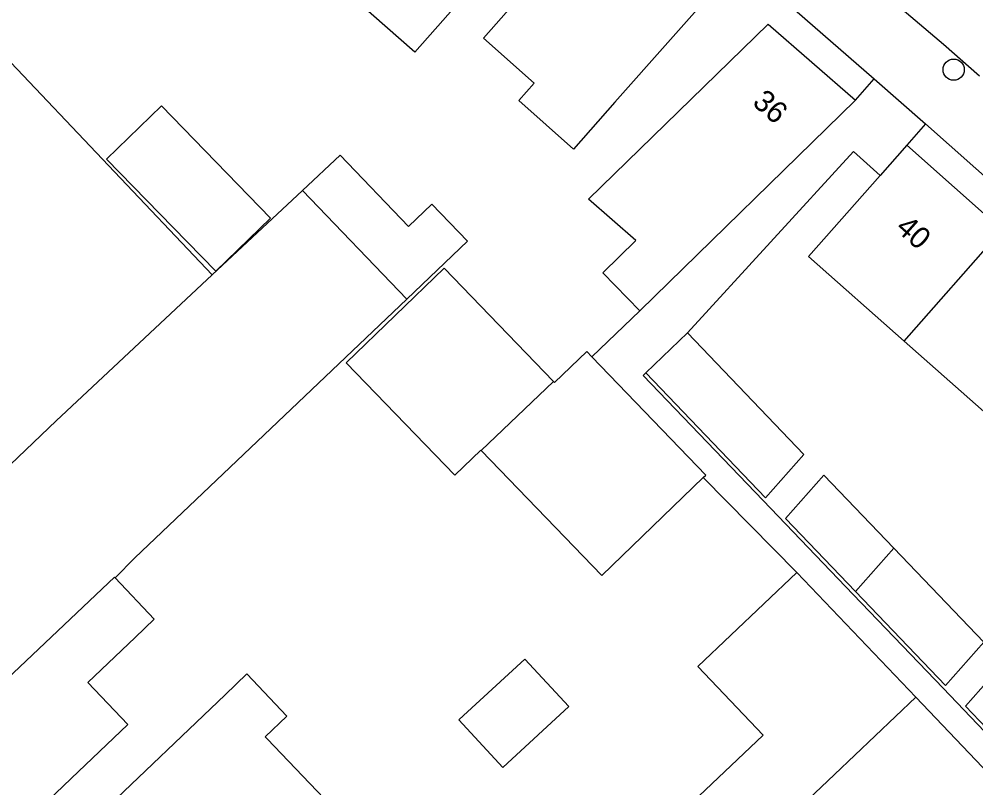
# Model space of a CAD drawing. Extents: x 162532 to 163264, y 381233 to 382042.
# Drawn here: x 162910.58 to 162954.65, y 381503.3 to 381538.72 of the extents above; entities that cross this region are included whole.
import ezdxf

# ---------------------------------------------------------------- set-up
doc = ezdxf.new("R2010")
doc.units = 0
for name, color, linetype in [('IMGEO_Boom', 7, 'Continuous'), ('IMGEO_Pand', 7, 'Continuous'), ('IMGEO_Pand_nummerreeks', 7, 'Continuous'), ('IMGEO_Rijbaan_lokaal_open', 7, 'Continuous'), ('IMGEO_Voetpad_open', 7, 'Continuous')]:
    doc.layers.add(name, color=color, linetype=linetype)

msp = doc.modelspace()

# ---------------------------------------------------------------- linework, layer by layer
at = {"layer": 'IMGEO_Boom'}
msp.add_circle((162953.626, 381536.396), 0.489, dxfattribs=at)
at = {"layer": 'IMGEO_Pand'}
for points in [[(162938.022, 381544.713), (162942.899, 381540.407), (162938.024, 381534.891), (162936.119, 381532.736), (162933.593, 381534.968), (162934.309, 381535.778), (162931.961, 381537.853), (162938.022, 381544.713)], [(162931.392, 381540.137), (162928.799, 381537.202), (162926.169, 381539.525), (162928.721, 381542.414)], [(162939.164, 381525.28), (162937.46, 381527.026), (162938.992, 381528.523), (162936.812, 381530.428), (162945.075, 381538.498), (162949.098, 381534.983)], [(162919.474, 381526.944), (162909.923, 381537.019), (162909.814, 381536.915)], [(162949.098, 381534.983), (162939.164, 381525.28)], [(162917.675, 381529.123), (162914.607, 381532.277), (162917.129, 381534.729), (162922.161, 381529.555), (162919.639, 381527.103), (162917.675, 381529.123)], [(162951.47, 381532.913), (162950.238, 381531.519)], [(162955.868, 381529.014), (162951.47, 381532.913)], [(162928.435, 381525.823), (162931.233, 381528.485), (162929.583, 381530.201), (162928.517, 381529.172), (162925.367, 381532.449), (162923.628, 381530.824)], [(162950.238, 381531.519), (162946.937, 381527.784), (162951.342, 381523.892)], [(162923.628, 381530.824), (162919.474, 381526.944)], [(162928.435, 381525.823), (162923.628, 381530.824)], [(162951.342, 381523.892), (162955.783, 381528.918), (162955.868, 381529.014)], [(162901.67, 381508.333), (162901.466, 381508.547), (162907.675, 381514.471), (162907.001, 381515.177), (162912.284, 381520.218), (162919.474, 381526.944)], [(162931.863, 381518.85), (162931.848, 381518.866), (162930.642, 381517.704), (162925.643, 381522.886), (162930.163, 381527.246), (162935.198, 381522.028)], [(162915.003, 381512.983), (162915.907, 381513.903), (162928.435, 381525.823)], [(162941.363, 381524.265), (162946.727, 381518.669), (162944.96, 381516.669), (162939.444, 381522.425)], [(162939.444, 381522.425), (162941.363, 381524.265)], [(162951.342, 381523.892), (162955.815, 381519.939)], [(162935.198, 381522.028), (162935.244, 381521.98), (162936.726, 381523.409), (162936.966, 381523.16)], [(162942.092, 381517.596), (162942.217, 381517.717), (162936.966, 381523.16)], [(162935.198, 381522.028), (162931.863, 381518.85)], [(162942.092, 381517.596), (162937.42, 381513.09), (162931.863, 381518.85)], [(162949.104, 381512.345), (162945.876, 381515.714), (162947.643, 381517.713), (162950.871, 381514.344)], [(162950.871, 381514.344), (162949.104, 381512.345)], [(162949.104, 381512.345), (162953.249, 381508.02), (162955.016, 381510.02), (162950.871, 381514.344)], [(162927.06, 381494.771), (162928.973, 381492.767), (162931.838, 381495.502), (162932.581, 381496.211), (162930.729, 381498.15), (162935.735, 381502.902), (162938.652, 381499.847), (162944.855, 381505.737), (162941.842, 381508.894), (162946.401, 381513.222)], [(162951.885, 381507.475), (162946.401, 381513.222)], [(162905.639, 381504.174), (162914.973, 381513.014), (162915.003, 381512.983)], [(162915.003, 381512.983), (162916.796, 381511.073), (162915.915, 381510.232), (162913.74, 381508.157), (162915.584, 381506.224), (162912.972, 381503.732), (162909.354, 381500.28), (162905.639, 381504.174)], [(162933.871, 381509.239), (162935.892, 381507.051), (162933.071, 381504.445), (162932.855, 381504.246), (162930.834, 381506.434), (162931.05, 381506.633), (162933.871, 381509.239)], [(162959.161, 381505.694), (162955.933, 381509.063), (162954.167, 381507.063), (162957.395, 381503.695)], [(162923.972, 381503.5), (162924.946, 381502.479), (162921.897, 381499.569), (162920.938, 381500.605), (162920.304, 381500), (162918.305, 381498.093), (162914.687, 381494.641), (162910.779, 381498.736), (162912.104, 381500), (162914.397, 381502.188), (162920.065, 381507.596), (162921.066, 381508.551), (162922.916, 381506.613), (162921.914, 381505.657), (162922.01, 381505.557), (162923.972, 381503.5)], [(162935.374, 381491.799), (162948.134, 381503.914), (162951.885, 381507.475)], [(162956.799, 381502.326), (162951.885, 381507.475)]]:
    msp.add_lwpolyline(points, dxfattribs=at)
at = {"layer": 'IMGEO_Rijbaan_lokaal_open'}
msp.add_lwpolyline([(162954.811, 381536.096), (162953.154, 381537.552), (162948.645, 381541.401), (162948.19, 381541.79)], dxfattribs=at)
at = {"layer": 'IMGEO_Voetpad_open'}
for points in [[(162938.022, 381544.713), (162938.851, 381545.67), (162949.96, 381535.97)], [(162949.098, 381534.983), (162949.96, 381535.97)], [(162949.96, 381535.97), (162952.337, 381533.894)], [(162952.337, 381533.894), (162951.47, 381532.913)], [(162952.337, 381533.894), (162990.515, 381500), (162992.639, 381498.114), (162991.799, 381497.161)], [(162950.238, 381531.519), (162949.019, 381532.617), (162941.363, 381524.265)], [(162936.966, 381523.16), (162939.164, 381525.28)], [(162939.444, 381522.425), (162939.321, 381522.307), (162944.847, 381516.541), (162948.991, 381512.217), (162953.136, 381507.892), (162957.281, 381503.566), (162961.425, 381499.243), (162965.57, 381494.917), (162969.718, 381490.59), (162973.859, 381486.269), (162977.616, 381482.348), (162977.739, 381482.466)], [(162946.401, 381513.222), (162942.092, 381517.596)]]:
    msp.add_lwpolyline(points, dxfattribs=at)

# ---------------------------------------------------------------- texts
at = {"layer": 'IMGEO_Pand_nummerreeks'}
for s, rotation, p in [('36', 318.8554, (162944.305, 381534.814)), ('40', 318.3689, (162950.902, 381529.029))]:
    msp.add_text(s, height=1, rotation=rotation, dxfattribs=at).set_placement(p)

doc.saveas('drawing.dxf')
